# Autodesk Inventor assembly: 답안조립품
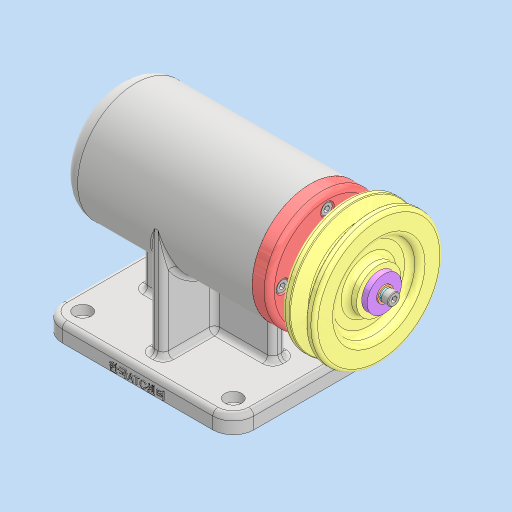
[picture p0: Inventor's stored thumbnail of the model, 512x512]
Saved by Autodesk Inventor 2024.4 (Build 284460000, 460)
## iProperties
Created: 2026-08
Part Number: 답안조립품
Document SubType Name: Assembly
Designer: home
Author: home
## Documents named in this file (14)
- C:\Users\kimgi\Desktop\760803V1002\답안조립품.iam
- C:\Users\kimgi\Desktop\760803V1002\본체.ipt
- C:\Users\kimgi\Desktop\760803V1002\축.ipt
- C:\Users\kimgi\Desktop\760803V1002\깊은 홈 볼 베어링 6004.ipt
- C:\Users\kimgi\Desktop\760803V1002\평행 키 5x5x16.ipt
- C:\Users\kimgi\Desktop\760803V1002\V 벨트 풀리.ipt
- C:\Users\kimgi\Desktop\760803V1002\엔드 캡.ipt
- C:\Users\kimgi\Desktop\760803V1002\평 와셔 M4.ipt
- C:\Users\kimgi\Desktop\760803V1002\스프링 와셔 M4.ipt
- C:\Users\kimgi\Desktop\760803V1002\6각 구멍붙이 볼트 M4x12.ipt
- C:\Users\kimgi\Desktop\760803V1002\어댑터 슬리브.ipt
- C:\Users\kimgi\Desktop\760803V1002\스러스트 볼 베어링 51202.ipt
- C:\Users\kimgi\Desktop\760803V1002\커버.ipt
- C:\Users\kimgi\Desktop\760803V1002\오일 실 20 32 5.ipt
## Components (7 placed, 2 different names)
1. V 벨트 풀리:1
2. 6각 구멍붙이 볼트 M4x12:1
3. 6각 구멍붙이 볼트 M4x12:2
4. 6각 구멍붙이 볼트 M4x12:3
5. 6각 구멍붙이 볼트 M4x12:4
6. 6각 구멍붙이 볼트 M4x12:5
7. 6각 구멍붙이 볼트 M4x12:6
